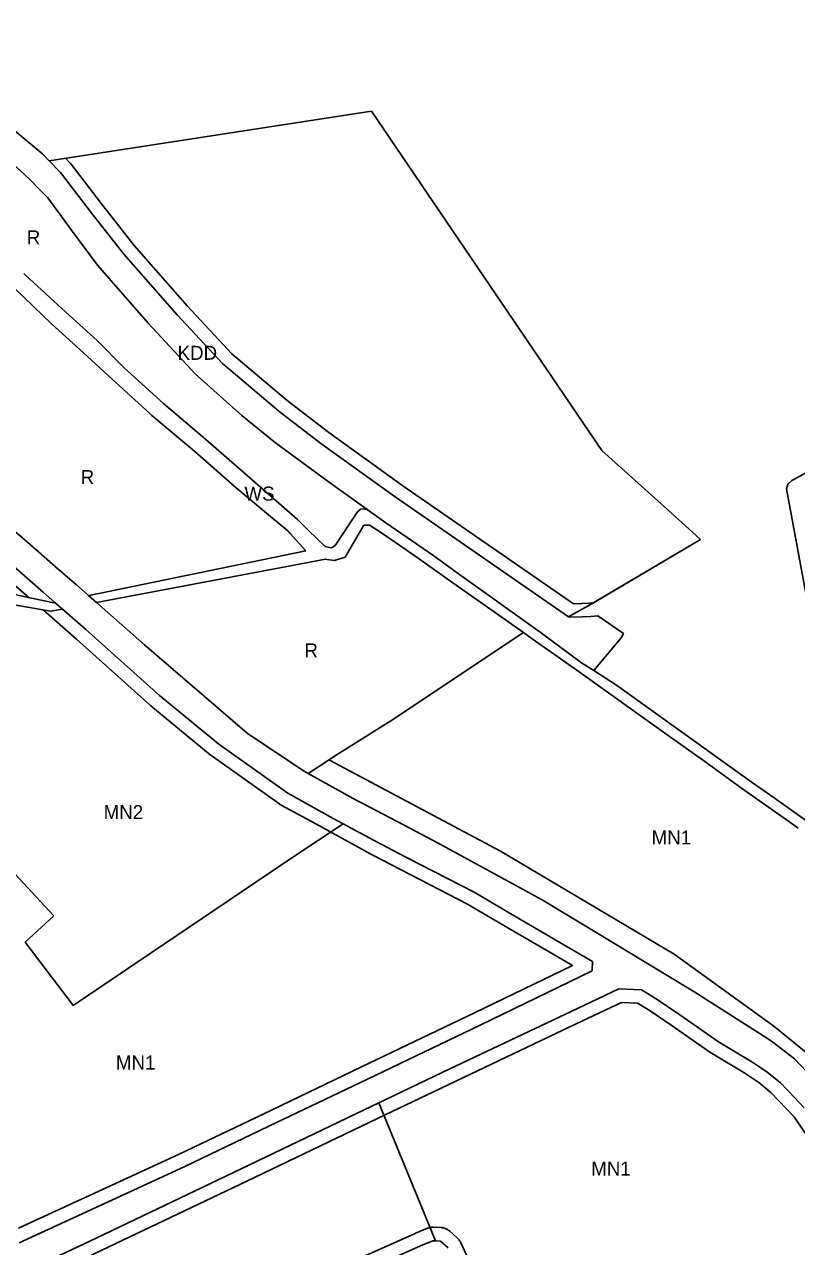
# Model space of a CAD drawing. Extents: x 7435758 to 7439981, y 5550649 to 5554049.
# Drawn here: x 7436821.5 to 7437108.2, y 5551911.1 to 5552364.7 of the extents above; entities that cross this region are included whole.
import ezdxf

# ---------------------------------------------------------------- set-up
doc = ezdxf.new("R2010")
doc.units = 0
for name, color, linetype in [('_Tereny_wyrok', 7, 'Continuous'), ('linie_rozgraniczające', 7, 'Continuous'), ('linie_zabudowy_nieprzekraczalne', 7, 'Continuous'), ('oznaczenia_przeznaczen', 7, 'Continuous')]:
    doc.layers.add(name, color=color, linetype=linetype)

msp = doc.modelspace()

# ---------------------------------------------------------------- linework, layer by layer
at = {"layer": '_Tereny_wyrok'}
for p, q in [((7436950.34, 5552332.41), (7436830.7, 5552314.09)), ((7437035.85, 5552206.58), (7436950.34, 5552332.41)), ((7436830.7, 5552314.09), (7436834.92, 5552309.73)), ((7436834.92, 5552309.73), (7436846.12, 5552295.03)), ((7436846.12, 5552295.03), (7436858.38, 5552279.36)), ((7436858.38, 5552279.36), (7436878.24, 5552256.92)), ((7436878.24, 5552256.92), (7436895.01, 5552238.78)), ((7436895.01, 5552238.78), (7436915.94, 5552221.19)), ((7436915.94, 5552221.19), (7436931.58, 5552209.19)), ((7436931.58, 5552209.19), (7436959.17, 5552189.34)), ((7437060.43, 5552184.47), (7437035.85, 5552206.58)), ((7436959.17, 5552189.34), (7437023.5, 5552144.84)), ((7437072.34, 5552173.76), (7437060.43, 5552184.47)), ((7437030.86, 5552148.9), (7437072.61, 5552173.52)), ((7437072.61, 5552173.52), (7437072.34, 5552173.76)), ((7437023.91, 5552145.07), (7437030.86, 5552148.9)), ((7437023.5, 5552144.84), (7437023.91, 5552145.07))]:
    msp.add_line(p, q, dxfattribs=at)
at = {"layer": 'linie_rozgraniczające'}
for p, q in [((7436828.32, 5552316.54), (7436754.67, 5552377.68)), ((7436950.34, 5552332.41), (7436830.7, 5552314.09)), ((7437035.85, 5552206.58), (7436950.34, 5552332.41)), ((7436830.7, 5552314.09), (7436828.32, 5552316.54)), ((7436816.7, 5552313.41), (7436823.53, 5552307.12)), ((7436834.92, 5552309.73), (7436830.7, 5552314.09)), ((7436823.53, 5552307.12), (7436827.24, 5552303.29)), ((7436846.12, 5552295.03), (7436834.92, 5552309.73)), ((7436827.24, 5552303.29), (7436830.12, 5552300.32)), ((7436830.12, 5552300.32), (7436838.94, 5552288.29)), ((7436858.38, 5552279.36), (7436846.12, 5552295.03)), ((7436838.94, 5552288.29), (7436848.57, 5552275.3)), ((7436848.57, 5552275.3), (7436867.5, 5552253.71)), ((7436878.24, 5552256.92), (7436858.38, 5552279.36)), ((7436821.84, 5552271.66), (7436821.22, 5552272.23)), ((7436836.85, 5552257.92), (7436821.84, 5552271.66)), ((7436817.87, 5552266.67), (7436831.59, 5552253.59)), ((7436848.47, 5552247.33), (7436836.85, 5552257.92)), ((7436831.59, 5552253.59), (7436843.39, 5552242.82)), ((7436867.5, 5552253.71), (7436884.94, 5552234.96)), ((7436895.01, 5552238.78), (7436878.24, 5552256.92)), ((7436858.46, 5552237.27), (7436848.47, 5552247.33)), ((7436843.39, 5552242.82), (7436854, 5552233.07)), ((7436873.11, 5552223.95), (7436858.46, 5552237.27)), ((7436884.94, 5552234.96), (7436902.24, 5552219.5)), ((7436915.94, 5552221.19), (7436895.01, 5552238.78)), ((7436854, 5552233.07), (7436868.01, 5552220.32)), ((7436888.83, 5552210.56), (7436873.11, 5552223.95)), ((7436931.58, 5552209.19), (7436915.94, 5552221.19)), ((7436868.01, 5552220.32), (7436868.82, 5552219.58)), ((7436868.82, 5552219.58), (7436884.81, 5552206.12)), ((7436902.24, 5552219.5), (7436914.77, 5552209.39)), ((7436904.23, 5552197.29), (7436888.83, 5552210.56)), ((7436914.77, 5552209.39), (7436934.3, 5552195.03)), ((7436959.17, 5552189.34), (7436931.58, 5552209.19)), ((7436884.81, 5552206.12), (7436900.09, 5552192.66)), ((7437060.43, 5552184.47), (7437035.85, 5552206.58)), ((7437116.22, 5552200.66), (7437106.53, 5552195.37)), ((7436922.86, 5552180.92), (7436904.23, 5552197.29)), ((7436934.3, 5552195.03), (7436947.34, 5552185.68)), ((7437104.98, 5552194.03), (7437104.48, 5552192.3)), ((7437106.53, 5552195.37), (7437104.98, 5552194.03)), ((7436900.09, 5552192.66), (7436912.13, 5552182.68)), ((7437023.5, 5552144.84), (7436959.17, 5552189.34)), ((7437104.48, 5552192.3), (7437129.36, 5552057.48)), ((7436946.21, 5552184.68), (7436945.22, 5552183.81)), ((7436946.34, 5552184.7), (7436946.21, 5552184.68)), ((7436947.3, 5552184.9), (7436946.34, 5552184.7)), ((7436948.75, 5552184.67), (7436947.3, 5552184.9)), ((7436947.34, 5552185.68), (7436948.75, 5552184.67)), ((7436955.64, 5552179.73), (7436948.75, 5552184.67)), ((7436823.61, 5552171.62), (7436808.74, 5552184.32)), ((7436912.13, 5552182.68), (7436919.25, 5552176.78)), ((7436926.96, 5552176.9), (7436922.86, 5552180.92)), ((7436945.22, 5552183.81), (7436936.82, 5552171.22)), ((7437072.34, 5552173.76), (7437060.43, 5552184.47)), ((7436919.25, 5552176.78), (7436920.17, 5552175.74)), ((7436920.17, 5552175.74), (7436925.93, 5552169.25)), ((7436933.16, 5552170.85), (7436926.96, 5552176.9)), ((7436940.55, 5552166.89), (7436947.54, 5552178.8)), ((7436947.54, 5552178.8), (7436948.54, 5552178.78)), ((7436948.54, 5552178.78), (7436949.63, 5552178.77)), ((7436949.63, 5552178.77), (7436949.66, 5552178.77)), ((7436949.66, 5552178.77), (7436952.97, 5552176.78)), ((7436952.97, 5552176.78), (7436963.22, 5552169.7)), ((7436973.49, 5552167.41), (7436955.64, 5552179.73)), ((7436834.07, 5552162.48), (7436823.61, 5552171.62)), ((7436936.76, 5552171.13), (7436935.42, 5552170.37)), ((7436936.82, 5552171.22), (7436936.76, 5552171.13)), ((7437030.91, 5552148.93), (7437072.61, 5552173.52)), ((7437072.61, 5552173.52), (7437072.34, 5552173.76)), ((7436809.23, 5552170.75), (7436828.55, 5552153.85)), ((7436925.93, 5552169.25), (7436845.47, 5552152.77)), ((7436935.42, 5552170.37), (7436933.16, 5552170.85)), ((7436936.58, 5552165.71), (7436939.33, 5552166.53)), ((7436939.33, 5552166.53), (7436940.55, 5552166.89)), ((7436963.22, 5552169.7), (7436967.29, 5552166.81)), ((7436967.29, 5552166.81), (7436978.5, 5552158.85)), ((7436981.26, 5552161.81), (7436973.49, 5552167.41)), ((7436840.77, 5552156.63), (7436834.07, 5552162.48)), ((7436848.24, 5552150.08), (7436930.03, 5552165.6)), ((7436930.03, 5552165.6), (7436931.98, 5552165.97)), ((7436931.98, 5552165.97), (7436933.27, 5552166.22)), ((7436933.27, 5552166.22), (7436933.92, 5552166.12)), ((7436933.92, 5552166.12), (7436936.58, 5552165.71)), ((7436822.42, 5552152.11), (7436787.94, 5552159.56)), ((7436978.5, 5552158.85), (7437006.81, 5552138.93)), ((7437013.02, 5552139.1), (7436981.26, 5552161.81)), ((7436783.84, 5552155.27), (7436831.22, 5552146.85)), ((7436828.55, 5552153.85), (7436832.81, 5552150.13)), ((7436845.23, 5552152.72), (7436840.77, 5552156.63)), ((7436845.47, 5552152.77), (7436845.23, 5552152.72)), ((7436832.37, 5552150.04), (7436822.42, 5552152.11)), ((7436832.81, 5552150.13), (7436832.37, 5552150.04)), ((7436835.61, 5552147.69), (7436832.81, 5552150.13)), ((7436845.23, 5552152.72), (7436848.24, 5552150.08)), ((7436866.1, 5552134.44), (7436848.24, 5552150.08)), ((7437023.91, 5552145.07), (7437030.86, 5552148.9)), ((7437030.86, 5552148.9), (7437030.91, 5552148.93)), ((7436831.22, 5552146.85), (7436835.61, 5552147.69)), ((7436835.61, 5552147.69), (7436844.15, 5552140.22)), ((7437023.5, 5552144.84), (7437023.91, 5552145.07)), ((7437023.92, 5552144.8), (7437023.5, 5552144.84)), ((7437025.59, 5552144.65), (7437023.92, 5552144.8)), ((7437031.78, 5552144.9), (7437025.59, 5552144.65)), ((7437034.43, 5552145.22), (7437031.78, 5552144.9)), ((7437043.91, 5552138.61), (7437034.43, 5552145.22)), ((7436844.15, 5552140.22), (7436871.67, 5552115.67)), ((7437006.81, 5552138.93), (7436957.6, 5552106.19)), ((7437006.81, 5552138.93), (7437010.06, 5552136.65)), ((7437010.06, 5552136.65), (7437022.88, 5552127.61)), ((7437028.36, 5552127.76), (7437013.02, 5552139.1)), ((7437032.92, 5552124.86), (7437043.12, 5552137.04)), ((7437043.12, 5552137.04), (7437043.91, 5552138.61)), ((7436904.15, 5552101.63), (7436866.1, 5552134.44)), ((7437022.88, 5552127.61), (7437024.81, 5552126.26)), ((7437024.81, 5552126.26), (7437024.86, 5552126.22)), ((7437024.86, 5552126.22), (7437037.54, 5552117.2)), ((7437032.91, 5552124.85), (7437028.36, 5552127.76)), ((7437032.91, 5552124.85), (7437032.92, 5552124.86)), ((7437041.31, 5552119.46), (7437032.91, 5552124.85)), ((7437037.54, 5552117.2), (7437037.56, 5552117.18)), ((7437037.56, 5552117.18), (7437049.24, 5552108.86)), ((7437077.79, 5552093.32), (7437041.31, 5552119.46)), ((7436871.67, 5552115.67), (7436893.64, 5552097.51)), ((7437049.24, 5552108.86), (7437060.58, 5552100.78)), ((7436957.6, 5552106.19), (7436937.56, 5552093.73)), ((7436925.11, 5552087.7), (7436904.15, 5552101.63)), ((7437060.58, 5552100.78), (7437074.16, 5552091.09)), ((7436893.64, 5552097.51), (7436919.24, 5552079.31)), ((7436937.56, 5552093.73), (7436926.91, 5552086.7)), ((7437074.16, 5552091.09), (7437087.82, 5552081.28)), ((7437091.42, 5552083.6), (7437077.79, 5552093.32)), ((7436926.91, 5552086.7), (7436925.11, 5552087.7)), ((7436944.67, 5552076.81), (7436926.91, 5552086.7)), ((7437087.82, 5552081.28), (7437107.84, 5552067.1)), ((7437099.88, 5552077.62), (7437091.42, 5552083.6)), ((7436919.24, 5552079.31), (7436936.11, 5552069.99)), ((7436946.88, 5552075.65), (7436944.67, 5552076.81)), ((7437112.44, 5552068.75), (7437099.88, 5552077.62)), ((7436962.51, 5552067.44), (7436946.88, 5552075.65)), ((7436921.59, 5552055.85), (7436939.82, 5552067.99)), ((7436936.11, 5552069.99), (7436939.82, 5552067.99)), ((7436939.82, 5552067.99), (7436951.41, 5552061.74)), ((7436977.21, 5552059.72), (7436962.51, 5552067.44)), ((7437107.84, 5552067.1), (7437108.81, 5552066.42)), ((7436951.41, 5552061.74), (7436963.4, 5552055.53)), ((7436977.86, 5552059.36), (7436977.21, 5552059.72)), ((7436990.35, 5552052.51), (7436977.86, 5552059.36)), ((7436839.63, 5552000.51), (7436921.59, 5552055.85)), ((7436963.4, 5552055.53), (7436988.45, 5552042.61)), ((7436817.74, 5552049.55), (7436832.43, 5552033.88)), ((7437013.47, 5552039.85), (7436990.35, 5552052.51)), ((7436988.45, 5552042.61), (7437002.07, 5552034.61)), ((7437031.54, 5552029.05), (7437013.47, 5552039.85)), ((7436832.43, 5552033.88), (7436821.74, 5552024.08)), ((7437002.07, 5552034.61), (7437020.36, 5552023.94)), ((7437070.47, 5552005.57), (7437031.54, 5552029.05)), ((7436821.74, 5552024.08), (7436838.9, 5552001.48)), ((7437020.36, 5552023.94), (7437032.48, 5552016.87)), ((7437032.48, 5552016.87), (7437032.35, 5552013.43)), ((7437032.35, 5552013.43), (7436990.74, 5551993.3)), ((7437024.47, 5551998.39), (7437042.18, 5552006.77)), ((7437042.18, 5552006.77), (7437050.58, 5552006.33)), ((7437050.58, 5552006.33), (7437056.14, 5552003.08)), ((7437093.35, 5551990.97), (7437070.47, 5552005.57)), ((7436838.9, 5552001.48), (7436839.63, 5552000.51)), ((7437056.14, 5552003.08), (7437064.9, 5551997.13)), ((7436979.51, 5551977.03), (7437024.47, 5551998.39)), ((7437064.9, 5551997.13), (7437079.2, 5551987.14)), ((7436990.74, 5551993.3), (7436948.86, 5551973.25)), ((7437094.34, 5551990.32), (7437093.35, 5551990.97)), ((7437098.92, 5551987.32), (7437094.34, 5551990.32)), ((7437079.2, 5551987.14), (7437091.67, 5551979.69)), ((7437107.51, 5551980.83), (7437098.92, 5551987.32)), ((7437119.37, 5551968.13), (7437107.51, 5551980.83)), ((7436953.08, 5551964.39), (7436979.51, 5551977.03)), ((7437091.67, 5551979.69), (7437097.16, 5551975.95)), ((7437097.16, 5551975.95), (7437102.2, 5551971.89)), ((7436948.86, 5551973.25), (7436912.27, 5551955.75)), ((7437102.2, 5551971.89), (7437107.45, 5551966.38)), ((7436947.39, 5551961.66), (7436953.08, 5551964.39)), ((7436974.19, 5551913.22), (7436953.08, 5551964.39)), ((7437107.45, 5551966.38), (7437111.09, 5551962.57)), ((7436901.97, 5551939.94), (7436947.39, 5551961.66)), ((7436912.27, 5551955.75), (7436881.03, 5551940.82)), ((7436848.07, 5551914.24), (7436901.97, 5551939.94)), ((7436881.03, 5551940.82), (7436868.15, 5551934.9)), ((7436868.15, 5551934.9), (7436819.57, 5551912.53)), ((7436823.55, 5551902.55), (7436848.07, 5551914.24)), ((7436973.13, 5551913.27), (7436968.62, 5551911.41)), ((7436974.19, 5551913.22), (7436973.13, 5551913.27)), ((7436976, 5551913.14), (7436974.19, 5551913.22)), ((7436978.85, 5551910.62), (7436976, 5551913.14)), ((7436968.62, 5551911.41), (7436943.64, 5551900.28))]:
    msp.add_line(p, q, dxfattribs=at)
at = {"layer": 'linie_zabudowy_nieprzekraczalne'}
for points in [[(7436836.75, 5552315.03), (7436838.51, 5552313.21), (7436838.54, 5552313.18), (7436838.76, 5552312.93), (7436838.89, 5552312.76), (7436850.08, 5552298.08), (7436862.22, 5552282.56), (7436881.94, 5552260.28), (7436898.47, 5552242.41), (7436919.07, 5552225.09), (7436934.57, 5552213.21), (7436962.05, 5552193.43), (7437023.79, 5552150.71), (7437025.25, 5552149.7), (7437025.71, 5552149.66), (7437031.38, 5552149.89), (7437032.75, 5552150.06)], [(7436823.4, 5552151.73), (7436806.07, 5552166.86), (7436805.35, 5552167.41), (7436804.89, 5552167.44), (7436804.77, 5552167.34), (7436804.75, 5552167.31), (7436794.03, 5552158.09)], [(7436819.34, 5551917.93), (7436866.06, 5551939.44), (7436878.9, 5551945.35), (7436878.91, 5551945.35), (7436910.11, 5551960.26), (7436946.7, 5551977.76), (7436988.58, 5551997.81), (7437025.03, 5552015.44), (7437017.84, 5552019.62), (7436999.55, 5552030.29), (7436999.54, 5552030.3), (7436986.03, 5552038.23), (7436961.11, 5552051.09), (7436961.1, 5552051.09), (7436950.87, 5552056.39), (7436950.4, 5552056.64), (7436929.64, 5552067.95), (7436916.83, 5552074.93), (7436916.64, 5552075.04), (7436916.36, 5552075.22), (7436916.35, 5552075.23), (7436890.75, 5552093.43), (7436890.5, 5552093.62), (7436890.46, 5552093.65), (7436868.48, 5552111.81), (7436868.34, 5552111.94), (7436840.84, 5552136.47), (7436828.53, 5552147.33)], [(7436934.74, 5552091.63), (7436998.26, 5552057.84), (7437062.75, 5552019.65), (7437099.78, 5551992.9), (7437113.79, 5551981.52)], [(7437113.57, 5551950.23), (7437107.2, 5551959.4), (7437098.81, 5551968.2), (7437094.18, 5551971.93), (7437088.98, 5551975.47), (7437076.64, 5551982.85), (7437076.6, 5551982.87), (7437076.34, 5551983.04), (7437062.06, 5551993.01), (7437053.47, 5551998.85), (7437049.11, 5552001.4), (7437043.18, 5552001.71), (7437026.61, 5551993.87), (7436981.66, 5551972.52), (7436955.24, 5551959.88), (7436949.54, 5551957.15), (7436904.13, 5551935.43), (7436904.12, 5551935.43), (7436904.12, 5551935.43), (7436850.22, 5551909.73), (7436827.48, 5551898.88), (7436825.92, 5551894.92), (7436837.19, 5551861.91), (7436839.78, 5551855.65)], [(7436941.61, 5551904.85), (7436966.58, 5551915.98), (7436966.71, 5551916.03), (7436971.22, 5551917.89), (7436971.33, 5551917.94), (7436971.64, 5551918.04), (7436971.95, 5551918.13), (7436972.27, 5551918.2), (7436972.6, 5551918.24), (7436972.92, 5551918.27), (7436973.25, 5551918.27), (7436973.35, 5551918.26), (7436976.22, 5551918.14), (7436976.45, 5551918.12), (7436976.77, 5551918.08), (7436977.09, 5551918.02), (7436977.41, 5551917.94), (7436977.72, 5551917.84), (7436978.03, 5551917.71), (7436978.32, 5551917.57), (7436978.6, 5551917.41), (7436978.88, 5551917.23), (7436979.14, 5551917.03), (7436979.31, 5551916.89), (7436982.16, 5551914.36), (7436982.24, 5551914.29), (7436982.47, 5551914.06), (7436982.69, 5551913.82), (7436982.89, 5551913.56), (7436983.08, 5551913.29), (7436983.24, 5551913.01), (7436983.37, 5551912.74), (7436992.22, 5551893.94)]]:
    msp.add_lwpolyline(points, dxfattribs=at)

# ---------------------------------------------------------------- texts
at = {"layer": 'oznaczenia_przeznaczen'}
for s, p in [('R', (7436822.36, 5552283.02)), ('KDD', (7436878.35, 5552240.18)), ('R', (7436842.37, 5552194.07)), ('WS', (7436903.19, 5552187.94)), ('R', (7436925.45, 5552129.77)), ('MN2', (7436850.9, 5552069.74)), ('MN1', (7437054.4, 5552060.34)), ('MN1', (7436855.45, 5551976.81)), ('MN1', (7437031.96, 5551937.46))]:
    msp.add_text(s, height=5.2, dxfattribs=at).set_placement(p)

doc.saveas('drawing.dxf')
